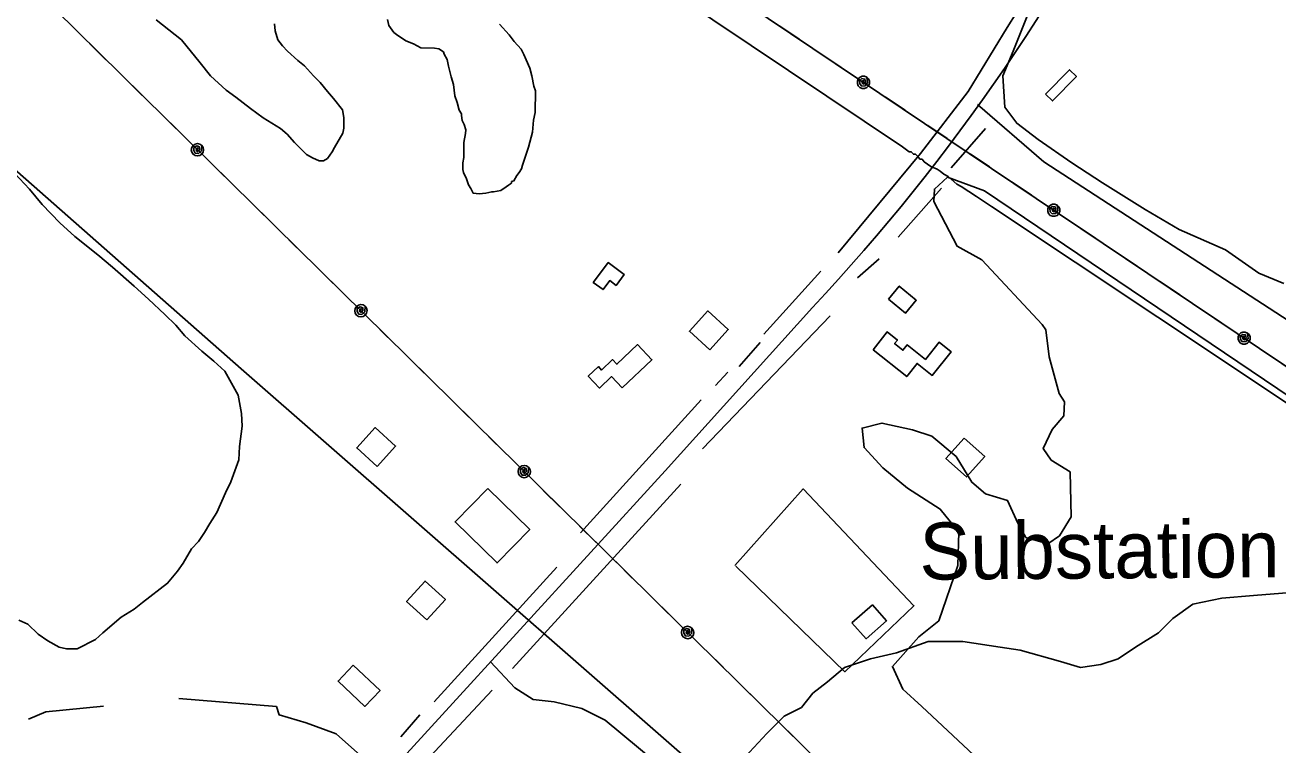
# Model space of a CAD drawing. Extents: x 3355677 to 3393573, y 612928 to 638357.
# Drawn here: x 3386504 to 3388329, y 628883 to 629932 of the extents above; entities that cross this region are included whole.
import ezdxf

# ---------------------------------------------------------------- set-up
doc = ezdxf.new("R2010")
doc.units = 0
for name, color, linetype in [('V-BLDG-OTLN', 7, 'Continuous'), ('V-ROAD-CNTR', 7, 'Continuous'), ('V-SITE-OTLN', 7, 'Continuous'), ('V-SITE-OTLN-IDEN', 7, 'Continuous'), ('V-SITE-VEGE', 7, 'Continuous'), ('V-TOPO-SHOR', 7, 'Continuous'), ('V-UTIL-LINE', 7, 'Continuous')]:
    doc.layers.add(name, color=color, linetype=linetype)

msp = doc.modelspace()

# ---------------------------------------------------------------- linework, layer by layer
at = {"layer": 'V-BLDG-OTLN'}
for points in [[(3387990.4, 629831.1), (3388025.4, 629866.8), (3388035.4, 629857), (3388000.4, 629821.3)], [(3387335, 629561.3), (3387353.5, 629585.9), (3387376.8, 629568.4), (3387365, 629552.7), (3387355.8, 629559.6), (3387345.9, 629546.5), (3387331.8, 629557)], [(3387761.6, 629532.6), (3387786.2, 629512.1), (3387802, 629531), (3387777.4, 629551.6)], [(3387501.3, 629458.9), (3387528.3, 629488.5), (3387498.7, 629515.4), (3387471.8, 629485.8)], [(3387739.1, 629458.8), (3387788.3, 629419.8), (3387803.4, 629438.9), (3387825.3, 629421.5), (3387852.7, 629456), (3387835.3, 629469.9), (3387815.5, 629444.8), (3387788.7, 629466), (3387782.6, 629458.3), (3387770.6, 629467.9), (3387774.6, 629473), (3387759.7, 629484.8)], [(3387374, 629403.4), (3387417.1, 629444.4), (3387396.1, 629466.4), (3387366.2, 629437.8), (3387359.8, 629444.5), (3387343.9, 629429.3), (3387339.2, 629434.3), (3387324.4, 629420.3), (3387340.8, 629403), (3387358.4, 629419.8)], [(3387016.9, 629288.9), (3387043.8, 629318.5), (3387014.3, 629345.4), (3386987.3, 629315.8)], [(3387872, 629330.2), (3387845.4, 629300.3), (3387875.3, 629273.7), (3387901.9, 629303.6)], [(3387178.3, 629256.8), (3387239.3, 629196.9), (3387191.6, 629148.3), (3387130.6, 629208.1)], [(3387089.5, 629065.4), (3387116.4, 629095), (3387086.8, 629121.9), (3387059.9, 629092.3)], [(3387708.5, 629061.1), (3387738.2, 629087.2), (3387758.7, 629063.9), (3387729, 629037.8)], [(3386982.3, 628999.4), (3387021.3, 628962.5), (3386999.2, 628939.2), (3386960.2, 628976.1)]]:
    msp.add_lwpolyline(points, close=True, dxfattribs=at)
at = {"layer": 'V-ROAD-CNTR'}
for points in [[(3387891.1, 629816.3), (3387987.8, 629732.9), (3388879.8, 629153.1)], [(3384610.8, 626130.4), (3385661.3, 627338.5), (3386895, 628690.1), (3387436.2, 629282.6), (3387651, 629520.5)], [(3387181.9, 629004.2), (3387217.3, 628966.4), (3387244.3, 628949.6), (3387274.7, 628946.2), (3387315.1, 628936.1), (3387348.9, 628919.2), (3387706.4, 628622.4), (3388003.3, 628352.5), (3388155.1, 628241.2), (3388387.9, 628018.5), (3388610.5, 627795.9), (3388954.6, 627502.4), (3389143.5, 627313.5), (3389187.4, 627273), (3389207.6, 627262.9), (3389231.2, 627249.4), (3389258.2, 627246), (3389308.8, 627242.6), (3389372.9, 627252.8), (3389406.6, 627259.5), (3389440.4, 627266.2), (3389480.9, 627283.1)]]:
    msp.add_lwpolyline(points, dxfattribs=at)
msp.add_arc((3385556.5, 631487.8), 2873.5, 316.7935, 334.6188, dxfattribs=at)
at = {"layer": 'V-SITE-OTLN'}
msp.add_lwpolyline([(3387538.1, 629144.7), (3387637.6, 629256.1), (3387798.7, 629086), (3387698.1, 628989.8), (3387539.5, 629143.5)], dxfattribs=at)
at = {"layer": 'V-SITE-VEGE'}
for points in [[(3388337.2, 629555.6), (3388301.2, 629570.6), (3388252.2, 629604.4), (3388184.8, 629634.2), (3388135.6, 629663.4), (3388073.1, 629702.2), (3388028.5, 629731.2), (3387979.5, 629765), (3387948.5, 629788.9), (3387931.1, 629812.4), (3387928.2, 629858.1), (3387943.2, 629894.1), (3387968.4, 629957)], [(3386867.4, 629933.6), (3386868.3, 629923.7), (3386872.5, 629910.5), (3386879, 629901.6), (3386886.5, 629893.8), (3386901.7, 629880.5), (3386911.4, 629872.6), (3386924.4, 629858.2), (3386934.1, 629848.2), (3386944.9, 629834.9), (3386953.5, 629824.9), (3386966.5, 629808.3), (3386968.5, 629797.3), (3386968.3, 629781.9), (3386967.1, 629774.3), (3386954.7, 629753.6), (3386951.3, 629747.1), (3386944.6, 629737.3), (3386939.1, 629734.1), (3386932.5, 629734.2), (3386922.7, 629738.7), (3386914, 629743.2), (3386896.7, 629761), (3386885.9, 629773.2), (3386876.2, 629781), (3386851.2, 629796.7), (3386832.7, 629810.2), (3386811, 629826.9), (3386796.9, 629837), (3386774.2, 629858.1), (3386759.1, 629877), (3386732.2, 629910.3), (3386695.3, 629939.3)], [(3387195.2, 629933.3), (3387209.2, 629917.8), (3387216.7, 629907.8), (3387226.5, 629896.7), (3387230.7, 629889), (3387233.9, 629881.2), (3387239.2, 629869.1), (3387242.4, 629858.1), (3387245.4, 629842.7), (3387247.5, 629836.1), (3387247.1, 629804.3), (3387244.7, 629793.4), (3387243.4, 629775.8), (3387237.6, 629754), (3387228.5, 629727.8), (3387227.3, 629722.4), (3387223.9, 629716.9), (3387220.6, 629712.6), (3387216.1, 629705), (3387212.8, 629703.9), (3387212.7, 629701.7), (3387208.3, 629698.5), (3387205, 629696.4), (3387197.2, 629691), (3387186.2, 629688.9), (3387184, 629689), (3387175.2, 629686.9), (3387165.4, 629686), (3387156.6, 629687.2), (3387153.4, 629693.8), (3387150.2, 629699.3), (3387147, 629708.1), (3387142.8, 629717), (3387141.7, 629721.4), (3387141.9, 629731.2), (3387143.1, 629738.9), (3387143.4, 629760.8), (3387145.8, 629773.9), (3387145.9, 629779.4), (3387143.8, 629787.1), (3387140.6, 629792.7), (3387139.6, 629800.3), (3387139.6, 629802.5), (3387136.4, 629808.1), (3387133.3, 629819.1), (3387130.1, 629829), (3387128.1, 629845.5), (3387125, 629856.5), (3387120.8, 629871.9), (3387118.8, 629881.8), (3387114.5, 629889.5), (3387113.5, 629892.8), (3387107, 629897.3), (3387100.4, 629898.5), (3387080.7, 629898.8), (3387069.8, 629904.4), (3387058.9, 629908.9), (3387052.4, 629913.4), (3387046.9, 629916.8), (3387041.5, 629921.2), (3387034, 629931.2), (3387031.9, 629940)], [(3386481.5, 629724), (3386510.7, 629692.9), (3386529, 629670.7), (3386554.9, 629644), (3386576.6, 629624), (3386610.2, 629597.2), (3386631.8, 629579.3), (3386663.2, 629551.5), (3386683.8, 629532.6), (3386707.6, 629510.3), (3386723.8, 629494.7), (3386736.8, 629479.2), (3386761.7, 629456.9), (3386779, 629442.4), (3386795.3, 629427.9), (3386802.7, 629414.7), (3386814.5, 629392.6), (3386819.6, 629366.2), (3386820.4, 629347.5), (3386816.7, 629318), (3386815.4, 629298.3), (3386803.9, 629266.6), (3386796, 629250.3), (3386783.6, 629222), (3386773.5, 629205.7), (3386765.6, 629192.6), (3386756.7, 629179.6), (3386746.6, 629168.8), (3386734.3, 629148.1), (3386726.4, 629136.2), (3386711.9, 629118.8), (3386675.4, 629090.8), (3386663.2, 629081.1), (3386644.4, 629069.3), (3386617.7, 629046.7), (3386606.6, 629037), (3386580.1, 629023.1), (3386564.8, 629023.3), (3386553.8, 629025.7), (3386537.5, 629034.7), (3386523.4, 629044.7), (3386508.3, 629059.2), (3386495.2, 629064.9)], [(3387991.1, 628769.5), (3387810, 628939), (3387782.5, 628964.4), (3387767.4, 628997.5), (3387805.7, 629040.8), (3387835, 629064.2), (3387862.4, 629144.5), (3387864.2, 629193.3), (3387837, 629226.8), (3387789.2, 629257.1), (3387753.6, 629286.9), (3387726.2, 629316.4), (3387723.2, 629344.9), (3387752, 629352), (3387796.4, 629342.2), (3387824.6, 629333.1), (3387860.1, 629303.3), (3387883.2, 629265.8), (3387902.9, 629248.8), (3387935.1, 629239.5), (3387950.2, 629206.4), (3387961.7, 629185.6), (3387993.9, 629176.3), (3388010.6, 629187.9), (3388027.9, 629215.7), (3388026.3, 629280.9), (3387998.4, 629298.2), (3387986.8, 629314.9), (3388000, 629342.9), (3388017.1, 629362.6), (3388017.8, 629382.9), (3388010.1, 629395.4), (3387995.8, 629448.8), (3387990.9, 629488), (3387985.6, 629495.5), (3387897.7, 629590), (3387861.9, 629609.6), (3387827.8, 629674.7), (3387828.5, 629693), (3387847.4, 629710.5), (3387901.4, 629690.3), (3388445, 629323.5)]]:
    msp.add_lwpolyline(points, dxfattribs=at)
at = {"layer": 'V-TOPO-SHOR'}
for p, q in [((3387934.3, 629928.2), (3387982.4, 630004.8)), ((3387853, 629724), (3387902.8, 629781)), ((3387775.7, 629622.9), (3387838.9, 629694.1)), ((3387716.4, 629563.6), (3387748, 629591.3)), ((3387580.3, 629481.8), (3387663.3, 629573.6)), ((3387491, 629314.5), (3387676.8, 629508.3)), ((3387544.3, 629434.5), (3387574.7, 629469.3)), ((3387509.7, 629406.6), (3387527.7, 629426.1)), ((3387313.2, 629192.4), (3387488.9, 629385.8)), ((3387214.3, 628994.3), (3387459.4, 629263.1)), ((3387100.1, 628946.2), (3387278.6, 629142.4)), ((3387051.7, 628894.8), (3387079.3, 628926.8))]:
    msp.add_line(p, q, dxfattribs=at)
for points in [[(3387688.2, 629600), (3387808.5, 629744.7), (3387877.7, 629835), (3387934.3, 629928.2)], [(3387534.2, 628845.3), (3387584.6, 628899.8), (3387609.7, 628925), (3387634.9, 628937.5), (3387651.6, 628958.5), (3387672.6, 628975.3), (3387697.8, 628996.2), (3387735.5, 629008.8), (3387773.2, 629017.2), (3387819.3, 629034), (3387869.7, 629034), (3387924.2, 629025.6), (3387953.5, 629021.4), (3388012.2, 629004.6), (3388041.5, 628996.2), (3388070.9, 629000.4), (3388096.1, 629008.8), (3388121.2, 629025.6), (3388154.7, 629046.5), (3388175.7, 629067.5), (3388205.1, 629088.5), (3388247, 629096.9), (3388293.1, 629101.1), (3388347.6, 629105.2)], [(3387056, 628815.7), (3387072.6, 628843.5), (3387184.7, 628963.1)], [(3386728, 628950.8), (3386870.4, 628939), (3386874.3, 628927.1), (3386913.8, 628915.3), (3386957.3, 628899.4), (3386992.9, 628867.8)], [(3386509.4, 628920.7), (3386534.6, 628931.2), (3386618.6, 628939.6)]]:
    msp.add_lwpolyline(points, dxfattribs=at)
at = {"layer": 'V-UTIL-LINE'}
for points in [[(3385622.4, 630705.4), (3386548, 629954.5), (3387768, 628752.6), (3389034.8, 627575.9), (3389809.8, 626749.6), (3391123.1, 625365), (3391367.6, 625099.5)], [(3385281.5, 630652.9), (3385336.2, 630593.5), (3385906.5, 630235.5), (3386819, 629431.2), (3387681.7, 628676.3)], [(3387326, 630116.8), (3389341.2, 628762.3), (3391369.7, 627403.1)], [(3388411.8, 629334.7), (3388275.8, 629425.2), (3387911.8, 629667.8), (3387889.7, 629682.2), (3387867.6, 629696.7), (3387861.2, 629700.3), (3387848.5, 629711.2), (3387842.2, 629714.8), (3387836.7, 629719), (3387832.7, 629722.1), (3387823.3, 629725.7), (3387813.8, 629732.9), (3387810.6, 629736.5), (3387807.4, 629736.5), (3387804.3, 629740.2), (3387801.1, 629743.8), (3387797.9, 629743.8), (3387794.8, 629747.4), (3387791.6, 629747.4), (3387782.1, 629754.6), (3387285.3, 630087.8)], [(3387603.2, 629930.5), (3387631.4, 629911.5)], [(3386597.9, 629905.3), (3386622.1, 629881.4)], [(3387664.6, 629889.2), (3387692.8, 629870.3)], [(3387725.2, 629848.5), (3387725.1, 629851.4), (3387723.2, 629850), (3387723.3, 629847.3), (3387725.9, 629845.9), (3387728, 629848.7), (3387727.2, 629853.3), (3387723, 629854), (3387719.3, 629850.8), (3387719.9, 629846.3), (3387723, 629843), (3387727.8, 629843.5), (3387731.1, 629847.9), (3387730.2, 629856), (3387726.9, 629857.3), (3387723.4, 629857.3), (3387720.2, 629856), (3387717.7, 629853.5), (3387716.3, 629850.3), (3387716.3, 629846.8), (3387717.7, 629843.5), (3387720.1, 629841), (3387723.4, 629839.7), (3387726.9, 629839.7), (3387730.1, 629841), (3387732.6, 629843.5), (3387734, 629846.7), (3387734, 629850.2), (3387732.7, 629853.5), (3387730.2, 629856)], [(3386650.6, 629853.4), (3386674.8, 629829.5)], [(3387757.5, 629826.8), (3387785.7, 629807.8)], [(3386703.3, 629801.4), (3386727.5, 629777.6)], [(3387818.9, 629785.5), (3387847.2, 629766.5)], [(3386755.3, 629750.2), (3386755.8, 629753), (3386753.7, 629752.1), (3386753.3, 629749.3), (3386755.6, 629747.5), (3386758.1, 629749.8), (3386758.2, 629754.5), (3386754.2, 629756), (3386750, 629753.5), (3386749.8, 629749), (3386752.2, 629745.2), (3386757, 629744.8), (3386761.1, 629748.5), (3386761.6, 629756.6), (3386758.7, 629758.6), (3386755.3, 629759.2), (3386751.8, 629758.5), (3386748.9, 629756.5), (3386747, 629753.6), (3386746.3, 629750.1), (3386747, 629746.7), (3386749, 629743.8), (3386751.9, 629741.9), (3386755.4, 629741.2), (3386758.8, 629741.9), (3386761.7, 629743.9), (3386763.7, 629746.8), (3386764.3, 629750.3), (3386763.6, 629753.7), (3386761.6, 629756.6)], [(3387880.4, 629744.2), (3387908.6, 629725.2)], [(3386783.1, 629722.8), (3386807.3, 629699)], [(3387941.8, 629702.9), (3387970, 629683.9)], [(3386835.8, 629670.9), (3386860.1, 629647.1)], [(3388002.4, 629662.2), (3388002.3, 629665.1), (3388000.4, 629663.7), (3388000.5, 629661), (3388003.1, 629659.6), (3388005.2, 629662.3), (3388004.4, 629667), (3388000.2, 629667.6), (3387996.5, 629664.5), (3387997.1, 629659.9), (3388000.2, 629656.7), (3388005, 629657.2), (3388008.3, 629661.6), (3388007.4, 629669.7), (3388004.1, 629671), (3388000.6, 629671), (3387997.4, 629669.7), (3387994.9, 629667.2), (3387993.5, 629664), (3387993.5, 629660.5), (3387994.9, 629657.2), (3387997.3, 629654.7), (3388000.6, 629653.4), (3388004.1, 629653.4), (3388007.3, 629654.7), (3388009.8, 629657.2), (3388011.2, 629660.4), (3388011.2, 629663.9), (3388009.9, 629667.2), (3388007.4, 629669.7)], [(3388034.7, 629640.4), (3388062.9, 629621.5)], [(3386888.5, 629619), (3386912.8, 629595.1)], [(3388096.1, 629599.2), (3388124.4, 629580.2)], [(3386941.3, 629567.1), (3386965.5, 629543.2)], [(3388157.6, 629557.9), (3388185.8, 629538.9)], [(3386993.3, 629515.8), (3386993.8, 629518.7), (3386991.7, 629517.7), (3386991.3, 629515), (3386993.6, 629513.1), (3386996.1, 629515.4), (3386996.1, 629520.1), (3386992.1, 629521.6), (3386987.9, 629519.2), (3386987.7, 629514.6), (3386990.1, 629510.8), (3386994.9, 629510.4), (3386999, 629514.1), (3386999.6, 629522.2), (3386996.7, 629524.2), (3386993.2, 629524.8), (3386989.8, 629524.1), (3386986.9, 629522.1), (3386984.9, 629519.2), (3386984.3, 629515.8), (3386985, 629512.3), (3386987, 629509.4), (3386989.9, 629507.5), (3386993.3, 629506.8), (3386996.8, 629507.5), (3386999.7, 629509.5), (3387001.6, 629512.4), (3387002.3, 629515.9), (3387001.6, 629519.3), (3386999.6, 629522.2)], [(3388219, 629516.6), (3388247.2, 629497.6)], [(3387021.1, 629488.5), (3387045.3, 629464.6)], [(3388279.6, 629475.9), (3388279.5, 629478.7), (3388277.6, 629477.4), (3388277.7, 629474.6), (3388280.3, 629473.3), (3388282.4, 629476), (3388281.6, 629480.6), (3388277.4, 629481.3), (3388273.7, 629478.2), (3388274.3, 629473.6), (3388277.4, 629470.4), (3388282.2, 629470.9), (3388285.6, 629475.2), (3388284.6, 629483.3), (3388281.3, 629484.7), (3388277.8, 629484.7), (3388274.6, 629483.4), (3388272.1, 629480.9), (3388270.7, 629477.7), (3388270.7, 629474.1), (3388272.1, 629470.9), (3388274.5, 629468.4), (3388277.8, 629467), (3388281.3, 629467), (3388284.5, 629468.4), (3388287, 629470.9), (3388288.4, 629474.1), (3388288.4, 629477.6), (3388287.1, 629480.9), (3388284.6, 629483.3)], [(3387073.8, 629436.5), (3387098, 629412.7)], [(3388311.9, 629454.1), (3388340.1, 629435.2)], [(3387126.5, 629384.6), (3387150.7, 629360.7)], [(3387179.2, 629332.7), (3387203.4, 629308.8)], [(3387231.2, 629281.4), (3387231.7, 629284.3), (3387229.6, 629283.3), (3387229.2, 629280.6), (3387231.5, 629278.7), (3387234, 629281.1), (3387234.1, 629285.7), (3387230.1, 629287.2), (3387225.8, 629284.8), (3387225.7, 629280.2), (3387228.1, 629276.4), (3387232.9, 629276), (3387237, 629279.7), (3387237.5, 629287.8), (3387234.6, 629289.8), (3387231.1, 629290.4), (3387227.7, 629289.7), (3387224.8, 629287.7), (3387222.9, 629284.8), (3387222.2, 629281.4), (3387222.9, 629277.9), (3387224.9, 629275), (3387227.8, 629273.1), (3387231.3, 629272.4), (3387234.7, 629273.1), (3387237.6, 629275.1), (3387239.6, 629278), (3387240.2, 629281.5), (3387239.5, 629284.9), (3387237.5, 629287.8)], [(3387259, 629254.1), (3387283.2, 629230.2)], [(3387311.7, 629202.1), (3387335.9, 629178.3)], [(3387364.4, 629150.2), (3387388.6, 629126.3)], [(3387417.1, 629098.3), (3387441.4, 629074.4)], [(3387469.2, 629047), (3387469.6, 629049.9), (3387467.5, 629048.9), (3387467.1, 629046.2), (3387469.4, 629044.4), (3387471.9, 629046.7), (3387472, 629051.3), (3387468, 629052.8), (3387463.8, 629050.4), (3387463.6, 629045.8), (3387466, 629042), (3387470.8, 629041.6), (3387474.9, 629045.3), (3387475.5, 629053.4), (3387472.5, 629055.4), (3387469.1, 629056), (3387465.6, 629055.3), (3387462.7, 629053.4), (3387460.8, 629050.4), (3387460.2, 629047), (3387460.9, 629043.5), (3387462.8, 629040.6), (3387465.8, 629038.7), (3387469.2, 629038), (3387472.7, 629038.7), (3387475.6, 629040.7), (3387477.5, 629043.7), (3387478.2, 629047.1), (3387477.4, 629050.5), (3387475.5, 629053.4)], [(3387496.9, 629019.7), (3387521.2, 628995.8)], [(3387549.6, 628967.7), (3387573.9, 628943.9)], [(3387602.4, 628915.8), (3387626.6, 628892)]]:
    msp.add_lwpolyline(points, dxfattribs=at)

# ---------------------------------------------------------------- texts
at = {"layer": 'V-SITE-OTLN-IDEN'}
msp.add_text('Substation', height=83, rotation=0.3981, dxfattribs=at).set_placement((3387806.9, 629123.9))

doc.saveas('drawing.dxf')
